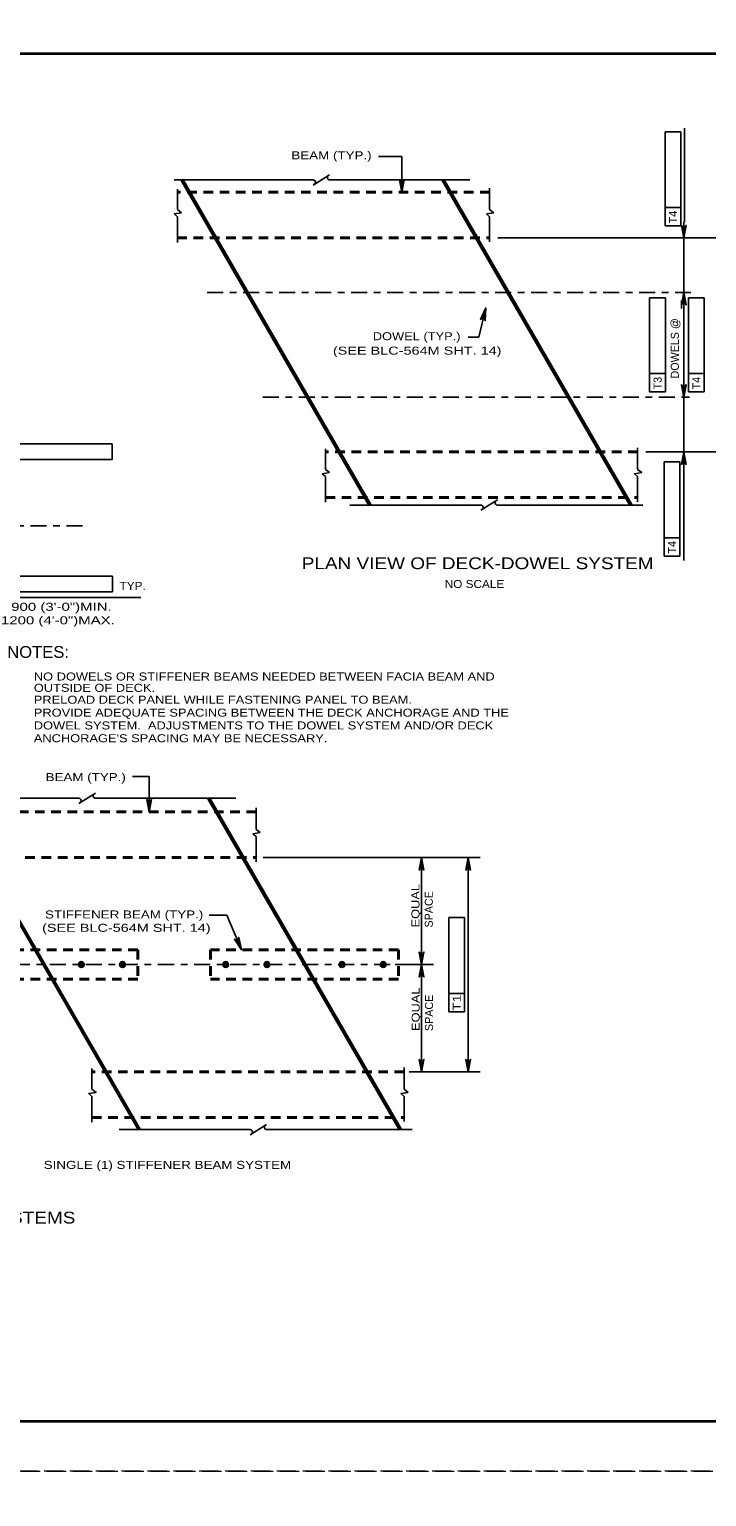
# Model space of a CAD drawing. Extents: x -11 to 79, y -154 to 0.
# Drawn here: x 49.26 to 59.41, y -132.38 to -110.38 of the extents above; entities that cross this region are included whole.
import ezdxf
from ezdxf.enums import TextEntityAlignment as Align

# ---------------------------------------------------------------- set-up
doc = ezdxf.new("R2010")
doc.units = 0
doc.header["$LTSCALE"] = 0.048
for name, pattern in [('DOT_DASHED', [7.7, 5, -1.2, 0.3, -1.2]), ('LONG_DASHED', [7.5, 6, -1.5]), ('MEDIUM_DASHED', [4.5, 3, -1.5])]:
    doc.linetypes.add(name, pattern=pattern)
for name, color, linetype, lineweight in [('1', 7, 'Continuous', 25), ('2', 7, 'Continuous', 35), ('3', 7, 'Continuous', 25), ('4', 7, 'Continuous', 25), ('63', 7, 'LONG_DASHED', 13), ('8', 7, 'Continuous', 35)]:
    doc.layers.add(name, color=color, linetype=linetype, lineweight=lineweight)

msp = doc.modelspace()

# ---------------------------------------------------------------- hatches: boundary and pattern name
at = {"layer": '4'}
for points in [[(54.8435, -112.82242), (54.84225, -112.81767), (54.84467, -112.81767)], [(59.09092, -114.447), (59.05092, -114.447), (59.07092, -114.327)], [(56.10108, -114.5575), (56.10117, -114.56233), (56.09892, -114.56183)], [(51.05367, -122.11533), (51.0525, -122.11058), (51.05492, -122.11058)], [(55.15842, -122.92025), (55.11842, -122.92025), (55.13842, -122.80025)], [(55.85875, -122.92025), (55.81875, -122.92025), (55.83875, -122.80025)], [(52.43525, -124.18225), (52.43233, -124.17833), (52.4345, -124.17742)], [(55.15842, -124.28158), (55.11842, -124.28158), (55.13842, -124.40158)], [(55.15842, -124.52158), (55.11842, -124.52158), (55.13842, -124.40158)], [(55.15842, -125.88283), (55.11842, -125.88283), (55.13842, -126.00283)], [(55.85875, -125.8905), (55.81875, -125.8905), (55.83875, -126.0105)]]:
    msp.add_hatch(color=256, dxfattribs=at).paths.add_polyline_path(points)

# ---------------------------------------------------------------- linework, layer by layer
at = {"layer": '1', "lineweight": 35}
msp.add_lwpolyline([(35.75, -131.25), (67.25, -131.25), (67.25, -110.75), (35.75, -110.75)], close=True, dxfattribs=at)
at = {"layer": '2', "lineweight": 53}
for p, q in [((51.545, -112.63758), (54.36417, -117.51475)), ((55.45842, -112.63758), (58.27758, -117.51475)), ((48.03183, -121.90983), (50.90317, -126.87733)), ((51.94517, -121.90983), (54.81658, -126.87733))]:
    msp.add_line(p, q, dxfattribs=at)
at = {"layer": '3'}
for p, q in [((53.51325, -112.63758), (51.43025, -112.63758)), ((53.75908, -112.56017), (53.51267, -112.715)), ((55.86333, -112.63758), (53.76183, -112.63758)), ((51.476, -113.08383), (51.476, -112.77483)), ((56.15892, -113.08383), (56.15892, -112.75992)), ((51.42725, -113.14842), (51.53758, -113.13142)), ((51.476, -113.19217), (51.42725, -113.14842)), ((51.53758, -113.13142), (51.476, -113.08383)), ((51.476, -113.5765), (51.476, -113.19217)), ((56.11017, -113.14842), (56.2205, -113.13142)), ((56.15892, -113.19217), (56.11017, -113.14842)), ((56.2205, -113.13142), (56.15892, -113.08383)), ((56.15892, -113.569), (56.15892, -113.19217)), ((56.45125, -114.35517), (56.41975, -114.30067)), ((57.35842, -115.92458), (57.32692, -115.87008)), ((53.69617, -116.97875), (53.69617, -116.66975)), ((58.37908, -116.97875), (58.37908, -116.65475)), ((53.6475, -117.04325), (53.75775, -117.02633)), ((53.75775, -117.02633), (53.69617, -116.97875)), ((56.27525, -117.43733), (56.02883, -117.59217)), ((56.02942, -117.51475), (54.06333, -117.51475)), ((58.45733, -117.51475), (56.278, -117.51475)), ((50.24583, -121.83242), (49.9995, -121.98725)), ((50, -121.90983), (47.91708, -121.90983)), ((52.35017, -121.90983), (50.24867, -121.90983)), ((52.65758, -122.37675), (52.65758, -122.05283)), ((52.60892, -122.44133), (52.71917, -122.42433)), ((52.65758, -122.48508), (52.60892, -122.44133)), ((52.71917, -122.42433), (52.65758, -122.37675)), ((52.65758, -122.86192), (52.65758, -122.48508)), ((50.19508, -126.272), (50.19508, -125.963)), ((54.878, -126.272), (54.878, -125.948)), ((54.93958, -126.3195), (54.878, -126.272)), ((54.82925, -126.3365), (54.93958, -126.3195)), ((54.878, -126.38025), (54.82925, -126.3365)), ((54.878, -126.75717), (54.878, -126.38025)), ((52.56842, -126.87733), (50.60233, -126.87733)), ((52.81425, -126.79992), (52.56783, -126.95475)), ((54.99633, -126.87733), (52.817, -126.87733))]:
    msp.add_line(p, q, dxfattribs=at)
at = {"layer": '3', "linetype": 'MEDIUM_DASHED', "lineweight": 40}
for p, q in [((56.15892, -112.82242), (51.476, -112.82242)), ((51.476, -113.50733), (56.15892, -113.50733)), ((58.37908, -116.71725), (53.69617, -116.71725)), ((53.69617, -117.40225), (58.37908, -117.40225)), ((52.65758, -122.11533), (47.97467, -122.11533)), ((47.97467, -122.80025), (52.65758, -122.80025)), ((50.8835, -124.18225), (50.8835, -124.62325)), ((51.97058, -124.18225), (51.97058, -124.62325)), ((54.79342, -124.18225), (51.97058, -124.18225)), ((54.79342, -124.18225), (54.79342, -124.62325)), ((50.8835, -124.62325), (48.06067, -124.62325)), ((54.79342, -124.62325), (51.97058, -124.62325)), ((54.878, -126.0105), (50.19508, -126.0105)), ((50.19508, -126.6955), (54.878, -126.6955))]:
    msp.add_line(p, q, dxfattribs=at)
at = {"layer": '3', "linetype": 'DOT_DASHED'}
for p, q in [((51.92275, -114.32792), (59.17525, -114.32683)), ((52.75808, -115.89733), (59.17525, -115.89625))]:
    msp.add_line(p, q, dxfattribs=at)
at = {"layer": '3'}
for points in [[(58.37908, -117.46392), (58.37908, -117.087), (58.33033, -117.04325), (58.44067, -117.02633), (58.37908, -116.97875)], [(53.69617, -117.47142), (53.69617, -117.087), (53.6475, -117.04325)], [(50.19508, -126.76467), (50.19508, -126.38025), (50.14633, -126.3365), (50.25667, -126.3195), (50.19508, -126.272)]]:
    msp.add_lwpolyline(points, dxfattribs=at)
at = {"layer": '3', "linetype": 'MEDIUM_DASHED', "lineweight": 40}
msp.add_lwpolyline([(50.8835, -124.18225), (48.06067, -124.18225), (48.06067, -124.62325)], dxfattribs=at)
at = {"layer": '3', "lineweight": 40}
for centre, radius in [((50.03507, -124.40274), 0.03333), ((50.03507, -124.40274), 0.025), ((50.03507, -124.40274), 0.01667), ((50.03507, -124.40274), 0.00833), ((50.65318, -124.40274), 0.03333), ((50.65318, -124.40274), 0.025), ((50.65318, -124.40274), 0.01667), ((50.65318, -124.40274), 0.00833), ((52.2009, -124.40274), 0.03333), ((52.2009, -124.40274), 0.02953), ((52.2009, -124.40274), 0.025), ((52.2009, -124.40274), 0.01667), ((52.2009, -124.40274), 0.00833), ((52.81901, -124.40274), 0.03333), ((52.81901, -124.40274), 0.02953), ((52.81901, -124.40274), 0.025), ((52.81901, -124.40274), 0.01667), ((52.81901, -124.40274), 0.00833), ((53.94499, -124.40274), 0.03333), ((53.94499, -124.40274), 0.02953), ((53.94499, -124.40274), 0.025), ((53.94499, -124.40274), 0.01667), ((53.94499, -124.40274), 0.00833), ((54.5631, -124.40274), 0.03333), ((54.5631, -124.40274), 0.02953), ((54.5631, -124.40274), 0.025), ((54.5631, -124.40274), 0.01667), ((54.5631, -124.40274), 0.00833)]:
    msp.add_circle(centre, radius, dxfattribs=at)
at = {"layer": '3'}
for centre in [(50.03507, -124.40274), (50.65318, -124.40274)]:
    msp.add_circle(centre, 0.02953, dxfattribs=at)
for centre, start, end in [((53.50987, -112.67376), 302.13276, 84.67141), ((53.76189, -112.60118), 120, 270), ((56.27807, -117.47836), 120, 270), ((56.02605, -117.55095), 302.13276, 84.67141), ((50.24862, -121.87345), 120, 270), ((49.9966, -121.94604), 302.13276, 84.67141), ((52.56499, -126.91354), 302.13276, 84.67141), ((52.81701, -126.84096), 120, 270)]:
    msp.add_arc(centre, 0.03637, start, end, dxfattribs=at)
at = {"layer": '4'}
for p, q in [((58.78983, -111.91592), (59.02608, -111.91592)), ((58.78983, -113.05233), (58.78983, -111.91592)), ((59.02608, -111.91592), (59.02608, -113.32792)), ((59.08108, -113.26683), (59.08108, -111.8635)), ((54.8435, -112.28892), (54.49167, -112.28892)), ((54.8435, -112.82242), (54.8435, -112.28892)), ((58.78983, -113.32792), (58.78983, -113.05233)), ((59.02608, -113.05233), (58.78983, -113.05233)), ((59.07092, -114.32683), (59.07092, -113.26683)), ((56.28108, -113.50733), (60.32258, -113.50733)), ((59.02608, -113.32792), (58.78983, -113.32792)), ((59.133, -113.50683), (59.25092, -113.50683)), ((59.07092, -115.8965), (59.07092, -114.327)), ((59.07867, -114.327), (59.17525, -114.327)), ((59.07867, -114.327), (59.16717, -114.327)), ((56.10108, -114.5575), (55.99783, -114.99625)), ((58.55867, -115.81758), (58.55867, -114.40558)), ((58.55867, -114.40558), (58.79483, -114.40558)), ((58.79483, -114.40558), (58.79483, -115.81758)), ((59.03658, -114.447), (59.03658, -114.567)), ((59.14008, -114.40558), (59.37625, -114.40558)), ((59.14008, -115.542), (59.14008, -114.40558)), ((59.37625, -114.40558), (59.37625, -115.81758)), ((55.99783, -114.99625), (55.83708, -114.99625)), ((58.79483, -115.542), (58.55867, -115.542)), ((59.07092, -115.7765), (59.07092, -115.6565)), ((59.14008, -115.81758), (59.14008, -115.542)), ((59.37625, -115.542), (59.14008, -115.542)), ((58.79483, -115.81758), (58.55867, -115.81758)), ((59.07092, -115.89642), (59.07092, -118.34458)), ((59.07792, -115.89642), (59.159, -115.89642)), ((59.37625, -115.81758), (59.14008, -115.81758)), ((49.10108, -116.59617), (50.49942, -116.59617)), ((50.49942, -116.59617), (50.49942, -116.83233)), ((59.25792, -116.717), (58.49925, -116.71725)), ((58.97683, -116.71717), (60.32258, -116.71717)), ((59.01658, -116.71708), (59.25092, -116.71708)), ((48.79867, -116.83233), (50.49942, -116.83233)), ((58.77475, -118.27842), (58.77475, -116.86633)), ((58.77475, -116.86633), (59.011, -116.86633)), ((59.011, -116.86633), (59.011, -118.27842)), ((59.011, -118.00275), (58.77475, -118.00275)), ((59.011, -118.27842), (58.77475, -118.27842)), ((49.10358, -118.579), (50.50192, -118.579)), ((50.50192, -118.579), (50.50192, -118.81517)), ((48.70792, -118.9015), (50.92625, -118.9015)), ((48.80117, -118.81517), (50.50192, -118.81517)), ((51.05367, -121.58183), (50.80492, -121.58183)), ((51.05367, -122.11533), (51.05367, -121.58183)), ((52.76117, -122.80025), (55.31842, -122.80025)), ((54.779, -122.80025), (56.01875, -122.80025)), ((55.13842, -122.80025), (55.13842, -124.40158)), ((55.83875, -122.80025), (55.83875, -126.0105)), ((52.21792, -123.66358), (51.95025, -123.66358)), ((52.43525, -124.18225), (52.21792, -123.66358)), ((55.54725, -123.6985), (55.78342, -123.6985)), ((55.54725, -124.81167), (55.54725, -123.6985)), ((55.78342, -123.6985), (55.78342, -125.1105)), ((55.19858, -124.40158), (54.74367, -124.40158)), ((54.779, -124.40158), (55.31842, -124.40158)), ((55.13842, -124.40158), (55.13842, -126.0105)), ((55.54725, -125.1105), (55.54725, -124.81167)), ((55.78342, -124.83492), (55.54725, -124.83492)), ((55.78342, -125.1105), (55.54725, -125.1105)), ((54.951, -126.0105), (56.01875, -126.0105))]:
    msp.add_line(p, q, dxfattribs=at)
at = {"layer": '4', "linetype": 'DOT_DASHED'}
for p, q in [((37.395, -117.8235), (50.09508, -117.8235)), ((54.66533, -124.40275), (47.37417, -124.40275))]:
    msp.add_line(p, q, dxfattribs=at)
at = {"layer": '4'}
for points in [[(54.8435, -112.82242), (54.87842, -112.636), (54.8685, -112.65033), (54.856, -112.65775), (54.8435, -112.65992), (54.831, -112.65775), (54.8185, -112.65033), (54.80858, -112.636), (54.8435, -112.82242), (54.8185, -112.65033), (54.831, -112.65775), (54.8435, -112.82242), (54.8435, -112.65992), (54.856, -112.65775), (54.8435, -112.82242), (54.8685, -112.65033)], [(59.07092, -113.50733), (59.10583, -113.32092), (59.09592, -113.33525), (59.08342, -113.34267), (59.07092, -113.34483), (59.05842, -113.34267), (59.04592, -113.33525), (59.036, -113.32092), (59.07092, -113.50733), (59.04592, -113.33525), (59.05842, -113.34267), (59.07092, -113.50733), (59.07092, -113.34483), (59.08342, -113.34267), (59.07092, -113.50733), (59.09592, -113.33525)], [(59.07092, -114.32683), (59.036, -114.51325), (59.04592, -114.49883), (59.05842, -114.4915), (59.07092, -114.48933), (59.08342, -114.4915), (59.09592, -114.49883), (59.10583, -114.51325), (59.07092, -114.32683), (59.09592, -114.49883), (59.08342, -114.4915), (59.07092, -114.32683), (59.07092, -114.48933), (59.05842, -114.4915), (59.07092, -114.32683), (59.04592, -114.49883)], [(56.10108, -114.5575), (56.02433, -114.73092), (56.03733, -114.71925), (56.05117, -114.71492), (56.06383, -114.71567), (56.0755, -114.72067), (56.086, -114.73067), (56.09242, -114.747), (56.10108, -114.5575), (56.086, -114.73067), (56.0755, -114.72067), (56.10108, -114.5575), (56.06383, -114.71567), (56.05117, -114.71492), (56.10108, -114.5575), (56.03733, -114.71925)], [(59.07092, -115.89625), (59.10583, -115.70983), (59.09592, -115.72417), (59.08342, -115.73158), (59.07092, -115.73375), (59.05842, -115.73158), (59.04592, -115.72417), (59.036, -115.70983), (59.07092, -115.89625), (59.04592, -115.72417), (59.05842, -115.73158), (59.07092, -115.89625), (59.07092, -115.73375), (59.08342, -115.73158), (59.07092, -115.89625), (59.09592, -115.72417)], [(59.07092, -116.71708), (59.036, -116.9035), (59.04592, -116.88908), (59.05842, -116.88167), (59.07092, -116.87958), (59.08342, -116.88167), (59.09592, -116.88908), (59.10583, -116.9035), (59.07092, -116.71708), (59.09592, -116.88908), (59.08342, -116.88167), (59.07092, -116.71708), (59.07092, -116.87958), (59.05842, -116.88167), (59.07092, -116.71708), (59.04592, -116.88908)], [(51.05367, -122.11533), (51.08858, -121.92892), (51.07867, -121.94325), (51.06617, -121.95067), (51.05367, -121.95283), (51.04117, -121.95067), (51.02867, -121.94325), (51.01875, -121.92892), (51.05367, -122.11533), (51.02867, -121.94325), (51.04117, -121.95067), (51.05367, -122.11533), (51.05367, -121.95283), (51.06617, -121.95067), (51.05367, -122.11533), (51.07867, -121.94325)], [(55.13842, -122.80025), (55.1035, -122.98667), (55.11342, -122.97233), (55.12592, -122.96492), (55.13842, -122.96275), (55.15092, -122.96492), (55.16342, -122.97233), (55.17333, -122.98667), (55.13842, -122.80025), (55.16342, -122.97233), (55.15092, -122.96492), (55.13842, -122.80025), (55.13842, -122.96275), (55.12592, -122.96492), (55.13842, -122.80025), (55.11342, -122.97233)], [(55.83875, -122.80025), (55.80383, -122.98667), (55.81375, -122.97233), (55.82625, -122.96492), (55.83875, -122.96275), (55.85125, -122.96492), (55.86375, -122.97233), (55.87367, -122.98667), (55.83875, -122.80025), (55.86375, -122.97233), (55.85125, -122.96492), (55.83875, -122.80025), (55.83875, -122.96275), (55.82625, -122.96492), (55.83875, -122.80025), (55.81375, -122.97233)], [(52.43525, -124.18225), (52.39542, -123.99683), (52.39183, -124.01392), (52.38317, -124.02558), (52.37242, -124.03242), (52.36008, -124.03525), (52.34567, -124.03325), (52.331, -124.02383), (52.43525, -124.18225), (52.34567, -124.03325), (52.36008, -124.03525), (52.43525, -124.18225), (52.37242, -124.03242), (52.38317, -124.02558), (52.43525, -124.18225), (52.39183, -124.01392)], [(55.13842, -124.40158), (55.1035, -124.21517), (55.11342, -124.2295), (55.12592, -124.23692), (55.13842, -124.23908), (55.15092, -124.23692), (55.16342, -124.2295), (55.17333, -124.21517), (55.13842, -124.40158), (55.16342, -124.2295), (55.15092, -124.23692), (55.13842, -124.40158), (55.13842, -124.23908), (55.12592, -124.23692), (55.13842, -124.40158), (55.11342, -124.2295)], [(55.13842, -124.40158), (55.1035, -124.588), (55.11342, -124.57367), (55.12592, -124.56625), (55.13842, -124.56408), (55.15092, -124.56625), (55.16342, -124.57367), (55.17333, -124.588), (55.13842, -124.40158), (55.16342, -124.57367), (55.15092, -124.56625), (55.13842, -124.40158), (55.13842, -124.56408), (55.12592, -124.56625), (55.13842, -124.40158), (55.11342, -124.57367)], [(55.13842, -126.0105), (55.17333, -125.82408), (55.16342, -125.83842), (55.15092, -125.84583), (55.13842, -125.848), (55.12592, -125.84583), (55.11342, -125.83842), (55.1035, -125.82408), (55.13842, -126.0105), (55.11342, -125.83842), (55.12592, -125.84583), (55.13842, -126.0105), (55.13842, -125.848), (55.15092, -125.84583), (55.13842, -126.0105), (55.16342, -125.83842)], [(55.83875, -126.0105), (55.87367, -125.82408), (55.86375, -125.83842), (55.85125, -125.84583), (55.83875, -125.848), (55.82625, -125.84583), (55.81375, -125.83842), (55.80383, -125.82408), (55.83875, -126.0105), (55.81375, -125.83842), (55.82625, -125.84583), (55.83875, -126.0105), (55.83875, -125.848), (55.85125, -125.84583), (55.83875, -126.0105), (55.86375, -125.83842)]]:
    msp.add_lwpolyline(points, dxfattribs=at)
for points in [[(54.8435, -112.82242), (54.84225, -112.81767), (54.84467, -112.81767)], [(59.09092, -114.447), (59.05092, -114.447), (59.07092, -114.327)], [(56.10108, -114.5575), (56.10117, -114.56233), (56.09892, -114.56183)], [(51.05367, -122.11533), (51.0525, -122.11058), (51.05492, -122.11058)], [(55.15842, -122.92025), (55.11842, -122.92025), (55.13842, -122.80025)], [(55.85875, -122.92025), (55.81875, -122.92025), (55.83875, -122.80025)], [(52.43525, -124.18225), (52.43233, -124.17833), (52.4345, -124.17742)], [(55.15842, -124.28158), (55.11842, -124.28158), (55.13842, -124.40158)], [(55.15842, -124.52158), (55.11842, -124.52158), (55.13842, -124.40158)], [(55.15842, -125.88283), (55.11842, -125.88283), (55.13842, -126.00283)], [(55.85875, -125.8905), (55.81875, -125.8905), (55.83875, -126.0105)]]:
    msp.add_lwpolyline(points, close=True, dxfattribs=at)
at = {"layer": '63'}
for points in [[(34, -132), (68, -132), (68, -110), (34, -110)], [(34, -154), (68, -154), (68, -132), (34, -132)]]:
    msp.add_lwpolyline(points, close=True, dxfattribs=at)

# ---------------------------------------------------------------- texts
at = {"layer": '4'}
for s, height, width, p in [('BEAM (TYP.)', 0.12, 1.25, (53.18533, -112.33008)), ('DOWEL (TYP.)', 0.12, 1.2, (54.40658, -115.0425)), ('(SEE BLC-564M SHT. 14)', 0.12, 1.35, (53.80842, -115.25833)), ('NO SCALE', 0.12, 1.1, (55.4855, -118.75683)), ('NOTES:', 0.1772, 1.05, (48.924, -119.80483)), ('NO DOWELS OR STIFFENER BEAMS NEEDED BETWEEN FACIA BEAM AND ', 0.12, 1.2, (49.32283, -120.14408)), ('OUTSIDE OF DECK.', 0.12, 1.2, (49.32283, -120.31408)), ('PRELOAD DECK PANEL WHILE FASTENING PANEL TO BEAM.', 0.12, 1.2, (49.32283, -120.49217)), ('PROVIDE ADEQUATE SPACING BETWEEN THE DECK ANCHORAGE AND THE ', 0.12, 1.2, (49.32283, -120.68608)), ('DOWEL SYSTEM.  ADJUSTMENTS TO THE DOWEL SYSTEM AND/OR DECK', 0.12, 1.2, (49.32283, -120.878)), ("ANCHORAGE'S SPACING MAY BE NECESSARY.", 0.12, 1.2, (49.32283, -121.06992)), ('BEAM (TYP.)', 0.12, 1.25, (49.49925, -121.65233)), ('STIFFENER BEAM (TYP.)', 0.12, 1.25, (49.49058, -123.712)), ('(SEE BLC-564M SHT. 14)', 0.12, 1.35, (49.44658, -123.91225))]:
    msp.add_text(s, height=height, dxfattribs=dict(at, width=width)).set_placement(p)
for s, p in [('T4', (58.96892, -113.19546)), ('DOWELS @', (58.99658, -115.16342)), ('T3', (58.73767, -115.68537)), ('T4', (59.31908, -115.68512)), ('T4', (58.95383, -118.14596))]:
    msp.add_text(s, height=0.12, rotation=90, dxfattribs=at).set_placement(p, align=Align.CENTER)
for s, height, width, p in [('PLAN VIEW OF DECK-DOWEL SYSTEM', 0.1772, 1.2, (55.97967, -118.47475)), ('900 (3\'-0")MIN.', 0.12, 1.4, (49.73775, -119.09883)), ('1200 (4\'-0")MAX.', 0.12, 1.4, (49.68379, -119.30158)), ('SINGLE (1) STIFFENER BEAM SYSTEM', 0.12, 1.25, (51.32725, -127.46658)), ('PLAN VIEWS OF ALTERNATE STIFFENER BEAM SYSTEMS', 0.1772, 1.2, (45.97279, -128.28583))]:
    msp.add_text(s, height=height, dxfattribs=dict(at, width=width)).set_placement(p, align=Align.CENTER)
for s, rotation, width, p in [('TYP.', 359.938, 1.1, (50.80494, -118.78504)), ('T1', 90, 1.3, (55.72625, -124.97429))]:
    msp.add_text(s, height=0.12, rotation=rotation, dxfattribs=dict(at, width=width)).set_placement(p, align=Align.CENTER)
at = {"layer": '8', "width": 1.2}
for p in [(55.10617, -123.84733), (55.10925, -125.39942)]:
    msp.add_text('EQUAL ', height=0.12, rotation=89.971, dxfattribs=at).set_placement(p)
at = {"layer": '8'}
for p in [(55.30617, -123.84742), (55.30925, -125.3995)]:
    msp.add_text('SPACE', height=0.12, rotation=89.971, dxfattribs=at).set_placement(p)

doc.saveas('drawing.dxf')
